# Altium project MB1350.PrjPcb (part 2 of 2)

## Sheet Audio.SchDoc: Audio
size A4; SheetNumber: 5; SheetTotal: 12
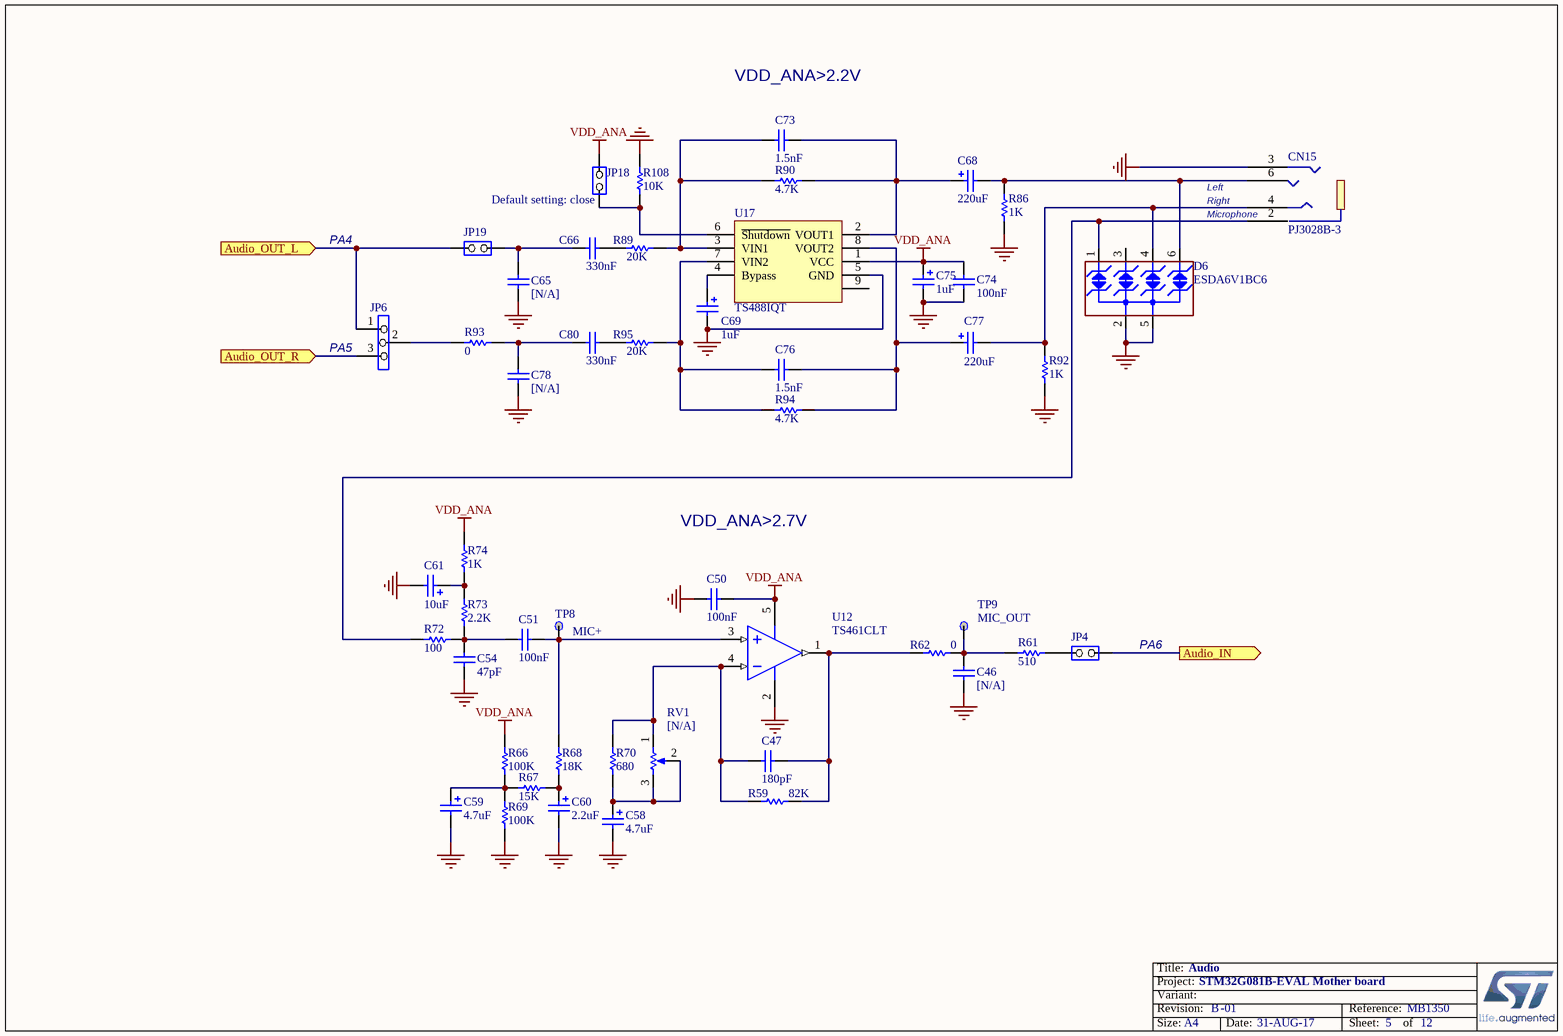
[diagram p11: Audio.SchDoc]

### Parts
C46  [N/A]  [0603C]
C47  180pF  [0603C]
C50  100nF  [0603C]
C51  100nF  [0603C]
C54  47pF  [0603C]
C58  4.7uF  [TAN-A]
C59  4.7uF  [TAN-A]
C60  2.2uF  [TAN-A]
C61  10uF  [TAN-A]
C65  [N/A]  [0603C]
C66  330nF  [0603C]
C68  220uF  [C310M-6]
C69  1uF  [TAN-A]
C73  1.5nF  [0603C]
C74  100nF  [0603C]
C75  1uF  [TAN-A]
C76  1.5nF  [0603C]
C77  220uF  [C310M-6]
C78  [N/A]  [0603C]
C80  330nF  [0603C]
CN15  PJ3028B-3  [PJ3028B]
D6  ESDA6V1BC6  [SOT23-6L]
JP4  (no value)  [SIP2]
JP6  (no value)  [SIP3]
JP18  (no value)  [SIP2]
JP19  (no value)  [SIP2]
R59  82K  [0603R]
R61  510  [0603R]
R62  0  [0603R]
R66  100K  [0603R]
R67  15K  [0603R]
R68  18K  [0603R]
R69  100K  [0603R]
R70  680  [0603R]
R72  100  [0603R]
R73  2.2K  [0603R]
R74  1K  [0603R]
R86  1K  [0603R]
R89  20K  [0603R]
R90  4.7K  [0603R]
R92  1K  [0603R]
R93  0  [0603R]
R94  4.7K  [0603R]
R95  20K  [0603R]
R108  10K  [0603R]
RV1  [N/A]  [PTF_3314J]
TP8  MIC+  [TP]
TP9  MIC_OUT  [TP]
U12  TS461CLT  [SOT23-5]
U17  TS488IQT  [DFN8_0R5_2X2]

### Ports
Audio_IN (out), Audio_OUT_L (in), Audio_OUT_R (in)

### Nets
GND: C46.2 C50.1 C54.2 C58.2 C59.2 C60.2 C61.2 C65.1 C69.2 C74.1 C75.2 C78.1 CN15.3 D6.2(IO2) D6.5(IO4) R69.2 R86.1 R92.1 R108.2 U12.2(VDD) U17.5(GND)
VDD_ANA: C50.2 C74.2 C75.1 JP18.2(NO) R66.1 R74.2 U12.5(VCC) U17.1(VCC)
PA4: JP6.1 JP19.2(NO) ; port Audio_OUT_L
PA5: JP6.3 ; port Audio_OUT_R
PA6: JP4.1(COMMON) ; port Audio_IN
NetC46_1: C46.1 R61.2 R62.1 TP9.1
NetC47_1: C47.1 R59.2 R70.1 RV1.1(BOT) U12.4(IN-)
NetC47_2: C47.2 R59.1 R62.2 U12.1(OUT)
NetC51_1: C51.1 C54.1 R72.1 R73.1
NetC51_2: C51.2 R68.2 TP8.1 U12.3(IN+)
NetC58_1: C58.1 R70.2 RV1.2(TAP) RV1.3(TOP)
NetC59_1: C59.1 R66.2 R67.1 R69.1
NetC60_1: C60.1 R67.2 R68.1
NetC61_1: C61.1 R73.2 R74.1
NetC65_2: C65.2 C66.1 JP19.1(COMMON)
NetC66_2: C66.2 R89.1
NetC68_1: C68.1 C73.2 R90.2 U17.2(VOUT1)
NetC68_2: C68.2 CN15.6 D6.6(NC) R86.2
NetC69_1: C69.1 U17.4(Bypass)
NetC73_1: C73.1 R89.2 R90.1 U17.3(VIN1)
NetC76_1: C76.1 R94.1 R95.2 U17.7(VIN2)
NetC76_2: C76.2 C77.1 R94.2 U17.8(VOUT2)
NetC77_2: C77.2 CN15.4 D6.4(IO3) R92.2
NetC78_2: C78.2 C80.1 R93.2
NetC80_2: C80.2 R95.1
NetCN15_2: CN15.2 D6.1(IO1) R72.2
NetJP4_2: JP4.2(NO) R61.1
NetJP6_2: JP6.2 R93.1
NetJP18_1: JP18.1(COMMON) R108.1 U17.6(~{Shutdown})

Not connected (* = marked no-connect by the designer): D6 3(GND); U17 9(~{Slug})

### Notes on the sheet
- VDD_ANA>2.2V
- PA4
- Default setting: close
- Left
- Right
- Microphone
- (near JP6) PA5
- VDD_ANA>2.7V
- (near JP4) PA6

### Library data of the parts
C46 = CAP: Capacitor; Value: 100nF
C47 C50 C51 C54 C65 C66 C73 C74 C76 C78 C80 = CAP: Capacitor; Value: 100pF
C58-C61 C69 = Cap Pol1: Polarized Capacitor (Radial); Value: 100pF
C68 C75 C77 = Cap Pol1: Polarized Capacitor (Radial); Value: 10uF
D6 = ESDA6V1BC6: 4-line ESD protection; Manuf_1: STM; Ref St: 9179034; Provided: ST; ECCN_US/EU: EAR99/NEC
JP4 JP18 JP19 = JP2
JP6 = Jumper3
R59 R61 R62 R66-R70 R72 R73 R89 R90 R93-R95 R108 = Res1: Resistor; Value: 1K
R74 R86 R92 = Res1: Resistor
RV1 = RV
TP8 TP9 = TP

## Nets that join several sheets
+3V3: MB1350_TOP (C14.2 U1.1), RS232_RS485 (7 pins), Peripherals (7 pins), Power (9 pins), Motor Control (CN1.28 R1.2), Extension connectors (CN4.14 CN9.22)
+3V3_SD: LCD_MicroSD (13 pins), Power (8 pins)
+5V: LCD_MicroSD (R96.1), ST_LINK_V2-1 (D1.1), Power (15 pins), Motor Control (CN1.25), Extension connectors (CN5.10)
D5V: ST_LINK_V2-1 (D3.1), Power (JP17.4), Extension connectors (CN5.16 CN9.20)
E5V: ST_LINK_V2-1 (D10.1), Power (C70.1 JP17.6 L2.3)
EXT_I2C_PWR: Peripherals (CN2.5 R12.2), Extension connectors (CN5.17)
GND: MB1350_TOP (C12.1 C14.1 U1.4 U1.5), LCD_MicroSD (16 pins), RS232_RS485 (14 pins), ST_LINK_V2-1 (40 pins), SWD (17 pins), Peripherals (20 pins), MCU (15 pins), Power (30 pins), Motor Control (25 pins), Extension connectors (7 pins), Audio (21 pins)
I2C_PU: Peripherals (R9.2 R10.2), Extension connectors (CN4.17)
U5V_ST_LINK: ST_LINK_V2-1 (C25.2 SB7.2 U5.1), Power (JP17.2)
VDD: MB1350_TOP (C12.2 R13.2 U1.8), LCD_MicroSD (8 pins), RS232_RS485 (5 pins), ST_LINK_V2-1 (R14.1), SWD (5 pins), Peripherals (R105.1 R106.1 R109.2 U19.3), MCU (JP15.1 L1.1 R84.2), Power (JP13.2 JP16.2 TP5.1), Extension connectors (CN4.18 CN5.18 CN10.21)
VDD_ANA: Peripherals (C91.2 RV3.1), Power (JP13.1), Extension connectors (CN4.16), Audio (8 pins)
VUSB_ST_LINK: ST_LINK_V2-1 (11 pins), Power (JP17.8)
PA0: Peripherals (SB38.1), MCU (U7.17), Extension connectors (CN10.9)
PA1: MCU (U7.18), Motor Control (JP1.1), Extension connectors (CN4.1)
PA2: MCU (U7.19), Motor Control (C9.2 R6.1), Extension connectors (CN5.8)
PA3: MCU (U7.20), Motor Control (JP2.1), Extension connectors (CN4.12)
PA4: MCU (U7.21), Extension connectors (CN10.6), Audio (JP6.1 JP19.2)
PA5: MCU (U7.22), Extension connectors (CN10.3), Audio (JP6.3)
PA6: MCU (U7.23), Motor Control (C8.2 R5.1), Extension connectors (CN10.4), Audio (JP4.1)
PA7: LCD_MicroSD (SB24.1), MCU (U7.24), Extension connectors (CN10.1)
PA8: MCU (U7.36), Motor Control (CN1.3), Extension connectors (CN5.1)
PA9: RS232_RS485 (JP10.3), MCU (U7.37), Motor Control (CN1.7), Extension connectors (CN5.3)
PA10: MCU (U7.42), Motor Control (CN1.11), Extension connectors (CN5.4)
PA11: MCU (U7.43), Extension connectors (CN9.4)
PA12: RS232_RS485 (SB16.1), MCU (U7.44), Extension connectors (CN9.5)
PA13: SWD (R48.2), MCU (U7.45), Extension connectors (CN10.5)
PA14: MCU (JP9.2 U7.46), Extension connectors (R39.2)
PA15: MCU (U7.47), Extension connectors (CN4.2)
PB0: MCU (U7.27), Motor Control (C3.2 CN1.34), Extension connectors (CN5.9)
PB1: MCU (U7.28), Motor Control (CN1.29), Extension connectors (CN4.10)
PB2: Peripherals (SB43.1), MCU (U7.29), Extension connectors (CN10.2)
PB3: LCD_MicroSD (SB25.1), MCU (R38.2), Extension connectors (CN10.8)
PB4: MCU (U7.58), Extension connectors (CN9.14)
PB5: MCU (U7.59), Motor Control (C2.2 CN1.33), Extension connectors (CN5.11)
PB6: Peripherals (CN2.3 R10.1), MCU (U7.60), Extension connectors (CN4.3)
PB7: Peripherals (CN2.1 R9.1), MCU (U7.61), Extension connectors (CN4.4)
PB8: MCU (U7.62), Extension connectors (CN10.7)
PB9: MCU (U7.63), Motor Control (CN1.21), Extension connectors (CN5.7)
PB10: MCU (U7.30), Motor Control (C7.2 R4.1), Extension connectors (CN4.11)
PB11: MCU (U7.31), Extension connectors (CN4.15 R26.2)
PB12: MCU (U7.32), Motor Control (JP3.2), Extension connectors (CN4.13)
PB13: MCU (U7.33), Extension connectors (CN4.8)
PB14: MCU (U7.34), Extension connectors (CN4.9)
PB15: MCU (U7.35), Motor Control (CN1.23), Extension connectors (CN5.2)
PC0: MCU (U7.13), Extension connectors (CN10.12)
PC1: MCU (U7.14), Motor Control (SB2.1), Extension connectors (CN5.12)
PC2: Peripherals (SB41.1), MCU (U7.15), Extension connectors (CN10.11)
PC3: Peripherals (SB37.1), MCU (U7.16), Extension connectors (CN10.14)
PC4: RS232_RS485 (JP10.1), MCU (U7.25), Extension connectors (CN9.13)
PC5: MCU (U7.26), Extension connectors (CN9.12)
PC6: MCU (U7.38), Motor Control (C1.2 CN1.31 SB1.2), Extension connectors (CN4.7)
PC7: Peripherals (SB40.1), MCU (U7.39), Extension connectors (CN9.3)
PC8: Peripherals (SB39.1), MCU (U7.48), Extension connectors (CN9.6)
PC9: LCD_MicroSD (SB8.1), MCU (U7.49), Extension connectors (CN9.7)
PC10: MCU (U7.64), Extension connectors (CN9.15)
PC11: MCU (U7.1), Extension connectors (CN9.16)
PC12: LCD_MicroSD (SB26.1), MCU (U7.2), Extension connectors (CN10.16)
PC13: Peripherals (SB42.1), MCU (U7.3), Extension connectors (R47.2)
PC14: MCU (R43.2 U7.4), Extension connectors (SB18.1)
PC15: MCU (R44.2 U7.5), Extension connectors (SB19.2)
PD0: MCU (U7.50), Motor Control (C4.2 CN1.27 SB2.2), Extension connectors (CN5.13)
PD1: MCU (U7.51), Extension connectors (CN9.8)
PD2: MCU (U7.52), Motor Control (CN1.5), Extension connectors (CN5.14)
PD3: MCU (U7.53), Motor Control (CN1.9), Extension connectors (CN5.15)
PD4: MCU (U7.54), Motor Control (CN1.13), Extension connectors (CN5.6)
PD5: Peripherals (SB36.2), MCU (U7.55), Extension connectors (CN9.9)
PD6: Peripherals (SB35.2), MCU (U7.56), Extension connectors (CN9.11)
PD8: Peripherals (SB34.2), MCU (SB11.2), Extension connectors (CN9.1)
PD9: Peripherals (SB33.2), MCU (SB10.2), Extension connectors (CN9.2)
PF0: MCU (R45.2 U7.10), Extension connectors (SB20.1)
PF1: MCU (R46.2 U7.11), Extension connectors (SB21.1)
PF2: MCU (SB23.2 U7.12), Extension connectors (R41.1)
PF3: MCU (JP15.2 U7.6), Extension connectors (SB44.2)
PF4: MCU (5 pins), Extension connectors (SB45.2)
RESET#: LCD_MicroSD (T2.2), ST_LINK_V2-1 (U2.18), SWD (R54.2), MCU (5 pins), Extension connectors (R11.1)
SWCLK: SWD (R50.2), MCU (JP9.1)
